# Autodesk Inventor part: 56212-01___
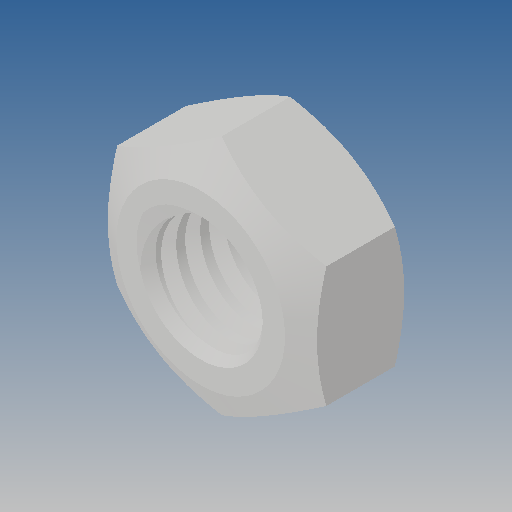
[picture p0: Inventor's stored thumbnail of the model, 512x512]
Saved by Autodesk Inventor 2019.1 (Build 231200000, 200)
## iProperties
Created: 2013-01
Part Number: 56212-01___
Material: Ogólny
Document SubType Name: Modeling
Designer: CADENGINEERING4
Density: 1 g/cm^3
Appearance: Domyślna
Author: CADENGINEERING4
Revision Number: ÈÎºÎ
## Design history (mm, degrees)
feature "NONE"
node "Bryła1"
